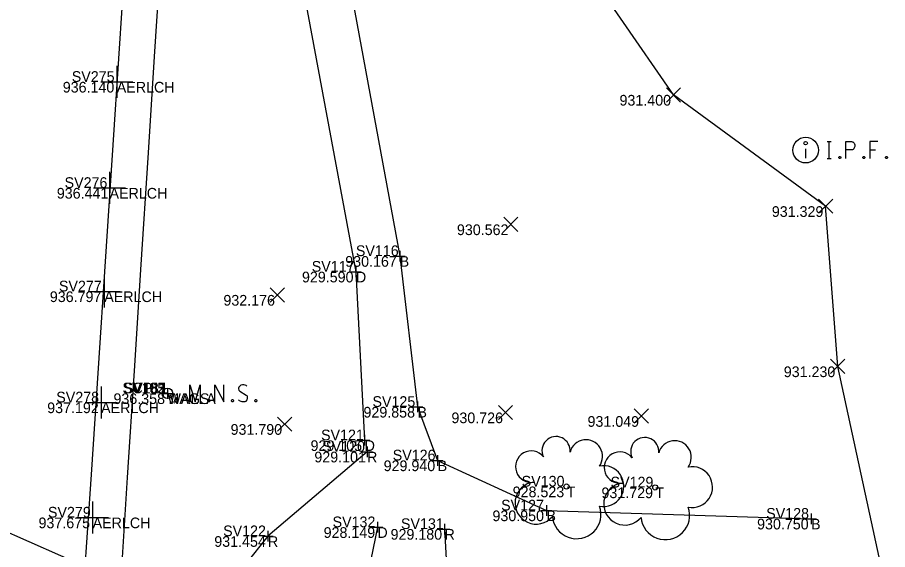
# Model space of a CAD drawing. Extents: x 1988835 to 1989144, y 657973 to 659339.
# Drawn here: x 1988993.8 to 1989075.4, y 658674.7 to 658724.6 of the extents above; entities that cross this region are included whole.
import ezdxf

# ---------------------------------------------------------------- set-up
doc = ezdxf.new("R2010")
doc.units = 0
for name, color, linetype in [('BR_X_SV_Abut_Text', 7, 'Continuous'), ('DR_X_Culvert', 7, 'Continuous'), ('DR_X_Ditch', 7, 'Continuous'), ('DR_X_Erosion_Control', 7, 'Continuous'), ('DT_X_Terrain_Boundary', 7, 'Continuous'), ('PV_X_EOP', 7, 'Continuous'), ('PV_X_Shoulder_Aggregate', 7, 'Continuous'), ('SV_P_Control_Cells_Set', 7, 'Continuous'), ('SV_X_Break_Lines', 7, 'Continuous'), ('SV_X_LiDAR_Check_Spots', 7, 'Continuous'), ('SV_X_Mon_Cells_Found', 7, 'Continuous'), ('SV_X_Random_Point', 7, 'Continuous'), ('SV_X_Shot_Marker', 7, 'Continuous'), ('SV_X_Text_Comment', 7, 'Continuous'), ('UT_X_Telecom', 7, 'Continuous'), ('UT_X_Telecom_Cells', 7, 'Continuous'), ('VG_X_Cells', 7, 'Continuous')]:
    doc.layers.add(name, color=color, linetype=linetype)

msp = doc.modelspace()

# ---------------------------------------------------------------- linework, layer by layer
at = {"layer": 'DR_X_Culvert'}
msp.add_line((1989019.511, 658664.679), (1988958.476, 658691.4), dxfattribs=at)
at = {"layer": 'DR_X_Ditch'}
for points in [[(1989020.098, 658798.635), (1989019.459, 658764.779), (1989020.113, 658729.809), (1989025.534, 658700.771), (1989026.349, 658684.974)], [(1989027.546, 658676.832), (1989026.05, 658669.563), (1989020.511, 658664.829), (1989025.324, 658663.598), (1989029.179, 658658.339), (1989037.179, 658655.839)]]:
    msp.add_lwpolyline(points, dxfattribs=at)
at = {"layer": 'DR_X_Erosion_Control'}
for points in [[(1989026.575, 658683.906), (1989017.283, 658675.992), (1989010.983, 658668.113), (1989009.487, 658661.132)], [(1989033.843, 658676.664), (1989034.634, 658662.648)]]:
    msp.add_lwpolyline(points, dxfattribs=at)
at = {"layer": 'DT_X_Terrain_Boundary'}
msp.add_lwpolyline([(1988964.615, 658494.73), (1988977.999, 658493.131), (1988991.982, 658491.879), (1988996.555, 658563.263), (1989005.478, 658554.052), (1989016.286, 658553.867), (1989055.687, 658591.481), (1989072.052, 658632.759), (1989075.239, 658671.007), (1989070.711, 658691.895), (1989069.571, 658706.908), (1989055.31, 658717.336), (1989045.383, 658731.746), (1989037.8, 658764.08), (1989044.504, 658795.249), (1989034.589, 658795.826), (1989024.049, 658796.33), (1989020.098, 658798.635), (1989011.648, 658798.864), (1989014.024, 658836.363)], dxfattribs=at)
at = {"layer": 'PV_X_EOP'}
msp.add_lwpolyline([(1988996.101, 658611.916), (1988996.761, 658621.894), (1988997.422, 658631.872), (1988998.083, 658641.85), (1988998.743, 658651.828), (1988999.404, 658661.806), (1989000.064, 658671.784), (1989000.725, 658681.763), (1989001.386, 658691.741), (1989002.046, 658701.719), (1989002.707, 658711.697), (1989003.367, 658721.675), (1989004.028, 658731.653), (1989004.689, 658741.632), (1989005.349, 658751.61), (1989006.01, 658761.588), (1989006.671, 658771.566), (1989007.331, 658781.544), (1989007.992, 658791.522), (1989008.652, 658801.5), (1989009.313, 658811.479), (1989009.974, 658821.457), (1989010.634, 658831.435), (1989011.295, 658841.413)], dxfattribs=at)
at = {"layer": 'PV_X_Shoulder_Aggregate'}
msp.add_lwpolyline([(1988999.654, 658611.634), (1989000.293, 658621.613), (1989000.932, 658631.593), (1989001.572, 658641.572), (1989002.211, 658651.552), (1989002.85, 658661.531), (1989003.49, 658671.511), (1989004.129, 658681.491), (1989004.768, 658691.47), (1989005.408, 658701.45), (1989006.047, 658711.429), (1989006.686, 658721.409), (1989007.326, 658731.388), (1989007.965, 658741.368), (1989008.604, 658751.347), (1989009.243, 658761.327), (1989009.883, 658771.306), (1989010.522, 658781.286), (1989011.161, 658791.265), (1989011.801, 658801.245), (1989012.44, 658811.225), (1989013.079, 658821.204), (1989013.719, 658831.184), (1989013.763, 658831.868)], dxfattribs=at)
at = {"layer": 'SV_P_Control_Cells_Set'}
for points in [[(1989009.949, 658688.574), (1989009.949, 658690.174), (1989010.456, 658688.574), (1989010.941, 658690.174), (1989010.941, 658688.574)], [(1989012.319, 658688.574), (1989012.319, 658690.174), (1989013.146, 658688.574), (1989013.146, 658690.174)], [(1989015.295, 658690.06), (1989015.273, 658690.085), (1989015.24, 658690.11), (1989015.141, 658690.148), (1989015.02, 658690.174), (1989014.931, 658690.174), (1989014.898, 658690.174), (1989014.755, 658690.136), (1989014.634, 658690.06), (1989014.557, 658689.959), (1989014.535, 658689.858), (1989014.535, 658689.783), (1989014.557, 658689.682), (1989014.645, 658689.594), (1989015.251, 658689.216), (1989015.306, 658689.166), (1989015.328, 658689.115), (1989015.35, 658689.04), (1989015.35, 658688.964), (1989015.339, 658688.889), (1989015.328, 658688.838), (1989015.306, 658688.775), (1989015.284, 658688.725), (1989015.262, 658688.687), (1989015.229, 658688.649), (1989015.196, 658688.624), (1989015.152, 658688.599), (1989015.119, 658688.586), (1989015.02, 658688.574), (1989014.865, 658688.574), (1989014.766, 658688.599), (1989014.623, 658688.687), (1989014.535, 658688.763)], [(1989011.713, 658688.788), (1989011.768, 658688.788), (1989011.801, 658688.763), (1989011.834, 658688.712), (1989011.834, 658688.649), (1989011.801, 658688.599), (1989011.768, 658688.574), (1989011.713, 658688.574), (1989011.68, 658688.599), (1989011.647, 658688.649), (1989011.647, 658688.712), (1989011.68, 658688.763), (1989011.713, 658688.788)], [(1989013.928, 658688.788), (1989013.983, 658688.788), (1989014.017, 658688.763), (1989014.049, 658688.712), (1989014.049, 658688.649), (1989014.017, 658688.599), (1989013.983, 658688.574), (1989013.928, 658688.574), (1989013.895, 658688.599), (1989013.862, 658688.649), (1989013.862, 658688.712), (1989013.895, 658688.763), (1989013.928, 658688.788)], [(1989016.111, 658688.788), (1989016.166, 658688.788), (1989016.199, 658688.763), (1989016.232, 658688.712), (1989016.232, 658688.649), (1989016.199, 658688.599), (1989016.166, 658688.574), (1989016.111, 658688.574), (1989016.078, 658688.599), (1989016.045, 658688.649), (1989016.045, 658688.712), (1989016.078, 658688.763), (1989016.111, 658688.788)]]:
    msp.add_lwpolyline(points, dxfattribs=at)
msp.add_circle((1989007.859, 658689.374), 0.497, dxfattribs=at)
at = {"layer": 'SV_X_Break_Lines'}
msp.add_lwpolyline([(1989024.049, 658796.33), (1989025.725, 658764.714), (1989024.613, 658729.526), (1989029.636, 658702.237), (1989031.3, 658688.106), (1989033.193, 658683.088), (1989043.396, 658678.399), (1989068.209, 658677.627)], dxfattribs=at)
at = {"layer": 'SV_X_LiDAR_Check_Spots'}
for p, q in [((1989003.106, 658720.059), (1989003.106, 658717.059)), ((1989001.606, 658718.559), (1989004.606, 658718.559)), ((1989003.106, 658718.559), (1989003.106, 658718.559)), ((1989002.427, 658710.121), (1989002.427, 658707.121)), ((1989000.927, 658708.621), (1989003.927, 658708.621)), ((1989002.427, 658708.621), (1989002.427, 658708.621)), ((1989001.934, 658700.428), (1989001.934, 658697.428)), ((1989000.434, 658698.928), (1989003.434, 658698.928)), ((1989001.934, 658698.928), (1989001.934, 658698.928)), ((1989001.641, 658690.02), (1989001.641, 658687.02)), ((1989000.141, 658688.52), (1989003.141, 658688.52)), ((1989001.641, 658688.52), (1989001.641, 658688.52)), ((1989000.844, 658679.238), (1989000.844, 658676.238)), ((1988999.344, 658677.738), (1989002.344, 658677.738)), ((1989000.844, 658677.738), (1989000.844, 658677.738))]:
    msp.add_line(p, q, dxfattribs=at)
at = {"layer": 'SV_X_Mon_Cells_Found'}
msp.add_line((1989067.7, 658712.28), (1989067.7, 658711.397), dxfattribs=at)
for points in [[(1989069.73, 658712.963), (1989070.083, 658712.963)], [(1989069.907, 658711.363), (1989069.907, 658712.963)], [(1989071.472, 658711.363), (1989071.472, 658712.963), (1989072.001, 658712.963), (1989072.056, 658712.951), (1989072.133, 658712.925), (1989072.167, 658712.9), (1989072.199, 658712.875), (1989072.244, 658712.812), (1989072.277, 658712.749), (1989072.299, 658712.648), (1989072.299, 658712.497), (1989072.288, 658712.447), (1989072.266, 658712.371), (1989072.222, 658712.283), (1989072.177, 658712.245), (1989072.144, 658712.22), (1989072.089, 658712.195), (1989072.001, 658712.182), (1989071.472, 658712.182)], [(1989074.481, 658712.963), (1989073.721, 658712.963), (1989073.721, 658711.363)], [(1989073.721, 658712.182), (1989074.261, 658712.182)], [(1989069.73, 658711.363), (1989070.083, 658711.363)], [(1989070.866, 658711.577), (1989070.921, 658711.577), (1989070.954, 658711.552), (1989070.987, 658711.502), (1989070.987, 658711.439), (1989070.954, 658711.388), (1989070.921, 658711.363), (1989070.866, 658711.363), (1989070.833, 658711.388), (1989070.8, 658711.439), (1989070.8, 658711.502), (1989070.833, 658711.552), (1989070.866, 658711.577)], [(1989073.114, 658711.577), (1989073.17, 658711.577), (1989073.203, 658711.552), (1989073.236, 658711.502), (1989073.236, 658711.439), (1989073.203, 658711.388), (1989073.17, 658711.363), (1989073.114, 658711.363), (1989073.081, 658711.388), (1989073.048, 658711.439), (1989073.048, 658711.502), (1989073.081, 658711.552), (1989073.114, 658711.577)], [(1989075.264, 658711.577), (1989075.319, 658711.577), (1989075.352, 658711.552), (1989075.385, 658711.502), (1989075.385, 658711.439), (1989075.352, 658711.388), (1989075.319, 658711.363), (1989075.264, 658711.363), (1989075.231, 658711.388), (1989075.198, 658711.439), (1989075.198, 658711.502), (1989075.231, 658711.552), (1989075.264, 658711.577)]]:
    msp.add_lwpolyline(points, dxfattribs=at)
for centre, radius in [((1989067.7, 658712.163), 1.2), ((1989067.7, 658712.815), 0.16)]:
    msp.add_circle(centre, radius, dxfattribs=at)
at = {"layer": 'SV_X_Random_Point'}
for p, q in [((1989054.643, 658716.669), (1989055.977, 658718.004)), ((1989054.643, 658718.004), (1989055.977, 658716.669)), ((1989068.904, 658706.241), (1989070.238, 658707.576)), ((1989068.904, 658707.576), (1989070.238, 658706.241)), ((1989039.394, 658704.536), (1989040.727, 658705.871)), ((1989039.394, 658705.871), (1989040.727, 658704.536)), ((1989017.505, 658697.926), (1989018.838, 658699.261)), ((1989017.505, 658699.261), (1989018.838, 658697.926)), ((1989070.044, 658691.227), (1989071.378, 658692.562)), ((1989070.044, 658692.562), (1989071.378, 658691.227)), ((1989038.887, 658686.912), (1989040.22, 658688.247)), ((1989038.887, 658688.247), (1989040.22, 658686.912)), ((1989051.623, 658686.573), (1989052.956, 658687.908)), ((1989051.623, 658687.908), (1989052.956, 658686.573)), ((1989018.175, 658685.823), (1989019.508, 658687.158)), ((1989018.175, 658687.158), (1989019.508, 658685.823))]:
    msp.add_line(p, q, dxfattribs=at)
at = {"layer": 'SV_X_Shot_Marker'}
for p, q in [((1989029.136, 658702.237), (1989030.136, 658702.237)), ((1989029.636, 658702.737), (1989029.636, 658701.737)), ((1989029.636, 658702.237), (1989029.636, 658702.237)), ((1989025.034, 658700.771), (1989026.034, 658700.771)), ((1989025.534, 658701.271), (1989025.534, 658700.271)), ((1989025.534, 658700.771), (1989025.534, 658700.771)), ((1989007.359, 658689.374), (1989008.359, 658689.374)), ((1989007.359, 658689.374), (1989008.359, 658689.374)), ((1989007.359, 658689.374), (1989008.359, 658689.374)), ((1989007.359, 658689.374), (1989008.359, 658689.374)), ((1989007.859, 658689.874), (1989007.859, 658688.874)), ((1989007.859, 658689.874), (1989007.859, 658688.874)), ((1989007.859, 658689.874), (1989007.859, 658688.874)), ((1989007.859, 658689.874), (1989007.859, 658688.874)), ((1989007.859, 658689.374), (1989007.859, 658689.374)), ((1989007.859, 658689.374), (1989007.859, 658689.374)), ((1989007.859, 658689.374), (1989007.859, 658689.374)), ((1989007.859, 658689.374), (1989007.859, 658689.374)), ((1989031.3, 658688.606), (1989031.3, 658687.606)), ((1989030.8, 658688.106), (1989031.8, 658688.106)), ((1989031.3, 658688.106), (1989031.3, 658688.106)), ((1989026.349, 658685.474), (1989026.349, 658684.474)), ((1989025.849, 658684.974), (1989026.849, 658684.974)), ((1989026.349, 658684.974), (1989026.349, 658684.974)), ((1989026.575, 658684.406), (1989026.575, 658683.406)), ((1989026.075, 658683.906), (1989027.075, 658683.906)), ((1989026.575, 658683.906), (1989026.575, 658683.906)), ((1989033.193, 658683.588), (1989033.193, 658682.588)), ((1989032.693, 658683.088), (1989033.693, 658683.088)), ((1989033.193, 658683.088), (1989033.193, 658683.088)), ((1989043.396, 658678.899), (1989043.396, 658677.899)), ((1989042.896, 658678.399), (1989043.896, 658678.399)), ((1989043.396, 658678.399), (1989043.396, 658678.399)), ((1989068.209, 658678.127), (1989068.209, 658677.127)), ((1989027.546, 658677.332), (1989027.546, 658676.332)), ((1989033.843, 658677.164), (1989033.843, 658676.164)), ((1989067.709, 658677.627), (1989068.709, 658677.627)), ((1989068.209, 658677.627), (1989068.209, 658677.627)), ((1989017.283, 658676.492), (1989017.283, 658675.492)), ((1989027.046, 658676.832), (1989028.046, 658676.832)), ((1989027.546, 658676.832), (1989027.546, 658676.832)), ((1989033.343, 658676.664), (1989034.343, 658676.664)), ((1989033.843, 658676.664), (1989033.843, 658676.664)), ((1989016.783, 658675.992), (1989017.783, 658675.992)), ((1989017.283, 658675.992), (1989017.283, 658675.992))]:
    msp.add_line(p, q, dxfattribs=at)
at = {"layer": 'VG_X_Cells'}
for centre in [(1989045.281, 658680.642), (1989053.597, 658680.556)]:
    msp.add_circle(centre, 0.24, dxfattribs=at)
for centre, radius, start, end in [((1989044.297, 658684.01), 1.317, 354.0047, 205.97412), ((1989052.613, 658683.923), 1.317, 354.0047, 205.97412), ((1989047.107, 658683.471), 1.553, 323.82996, 165.0376), ((1989055.423, 658683.385), 1.553, 323.82996, 165.0376), ((1989041.971, 658682.506), 1.471, 39.06254, 279.54124), ((1989050.287, 658682.42), 1.471, 39.06254, 279.54124), ((1989048.741, 658680.678), 1.915, 259.14531, 101.45961), ((1989057.057, 658680.591), 1.915, 259.14531, 101.45961), ((1989042.427, 658679.094), 1.974, 96.17219, 320.57371), ((1989050.743, 658679.007), 1.974, 96.17219, 320.57371), ((1989046.227, 658678.037), 2.284, 184.94757, 19.45715), ((1989054.543, 658677.95), 2.284, 184.94757, 19.45715)]:
    msp.add_arc(centre, radius, start, end, dxfattribs=at)

# ---------------------------------------------------------------- texts
at = {"layer": 'BR_X_SV_Abut_Text'}
for s, p in [('SV182', (1989003.656, 658689.374)), ('SV183', (1989003.663, 658689.374)), ('SV181', (1989003.772, 658689.374)), ('936.358', (1989002.799, 658688.374)), ('936.358', (1989002.799, 658688.374)), ('936.358', (1989002.799, 658688.374)), ('WALLA', (1989007.859, 658688.374)), ('WALLA', (1989007.859, 658688.374)), ('WALLA', (1989007.859, 658688.374))]:
    msp.add_text(s, height=1, dxfattribs=at).set_placement(p)
at = {"layer": 'SV_X_Text_Comment'}
for s, p in [('SV275', (1988998.888, 658718.559)), ('SV276', (1988998.217, 658708.621)), ('SV116', (1989025.529, 658702.237)), ('SV117', (1989021.388, 658700.771)), ('SV277', (1988997.684, 658698.928)), ('SV165', (1989003.641, 658689.374)), ('CP11', (1989004.575, 658689.374)), ('SV278', (1988997.435, 658688.52)), ('SV125', (1989027.083, 658688.106)), ('SV121', (1989022.262, 658684.974)), ('SV120', (1989022.368, 658683.906)), ('SV126', (1989028.982, 658683.088)), ('SV130', (1989041.073, 658680.642)), ('SV129', (1989049.409, 658680.556)), ('SV127', (1989039.147, 658678.399)), ('SV279', (1988996.656, 658677.738)), ('SV128', (1989064.003, 658677.627)), ('SV132', (1989023.343, 658676.832)), ('SV122', (1989013.08, 658675.992)), ('SV131', (1989029.756, 658676.664))]:
    msp.add_text(s, height=1, dxfattribs=at).set_placement(p)
at = {"layer": 'UT_X_Telecom'}
for s, p in [('AERLCH', (1989003.106, 658717.559)), ('AERLCH', (1989002.427, 658707.621)), ('B', (1989029.636, 658701.237)), ('D', (1989025.534, 658699.771)), ('AERLCH', (1989001.934, 658697.928)), ('MAGS', (1989007.859, 658688.374)), ('D', (1989007.859, 658688.374)), ('AERLCH', (1989001.641, 658687.52)), ('B', (1989031.3, 658687.106)), ('D', (1989026.349, 658683.974)), ('R', (1989026.575, 658682.906)), ('B', (1989033.193, 658682.088)), ('T', (1989045.281, 658679.642)), ('T', (1989053.597, 658679.556)), ('AERLCH', (1989000.844, 658676.738)), ('B', (1989043.396, 658677.399)), ('B', (1989068.209, 658676.627)), ('D', (1989027.546, 658675.832)), ('R', (1989033.843, 658675.664)), ('R', (1989017.283, 658674.992))]:
    msp.add_text(s, height=1, dxfattribs=at).set_placement(p)
at = {"layer": 'UT_X_Telecom_Cells'}
for s, p in [('936.140', (1988998.045, 658717.559)), ('931.400', (1989050.249, 658716.336)), ('936.441', (1988997.487, 658707.621)), ('931.329', (1989064.53, 658705.908)), ('930.562', (1989035.004, 658704.203)), ('930.167', (1989024.533, 658701.237)), ('929.590', (1989020.473, 658699.771)), ('936.797', (1988996.831, 658697.928)), ('932.176', (1989013.107, 658697.594)), ('931.230', (1989065.65, 658690.895)), ('936.358', (1989002.799, 658688.374)), ('936.358', (1989002.799, 658688.374)), ('937.192', (1988996.584, 658687.52)), ('929.858', (1989026.241, 658687.106)), ('930.726', (1989034.489, 658686.58)), ('931.049', (1989047.248, 658686.24)), ('931.790', (1989013.781, 658685.491)), ('929.105', (1989021.278, 658683.974)), ('929.101', (1989021.635, 658682.906)), ('929.940', (1989028.132, 658682.088)), ('928.523', (1989040.231, 658679.642)), ('931.729', (1989048.556, 658679.556)), ('937.675', (1988995.773, 658676.738)), ('930.950', (1989038.335, 658677.399)), ('930.750', (1989063.148, 658676.627)), ('928.149', (1989022.505, 658675.832)), ('929.180', (1989028.782, 658675.664)), ('931.454', (1989012.251, 658674.992))]:
    msp.add_text(s, height=1, dxfattribs=at).set_placement(p)

doc.saveas('drawing.dxf')
